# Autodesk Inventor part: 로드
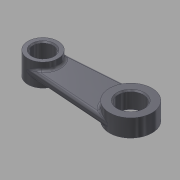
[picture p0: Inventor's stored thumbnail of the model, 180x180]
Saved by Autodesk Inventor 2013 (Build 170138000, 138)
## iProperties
Created: 2015-10
Part Number: 로드
Document SubType Name: Modeling
Designer: mdu
Density: 1 g/cm^3
Material: 강철, 연강
Mass: 2.59236 g
Surface Area: 22.2266 cm^2
Volume: 2.59236 cm^3
Author: mdu
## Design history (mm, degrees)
sketch "스케치1"
  geometry: L1 (13.821, 5.985)-(48.643, 8.478); L2 (48.643, -8.478)-(13.821, -5.985); C1 r 4 at (14.25, 0) reference; A1 r 6 centre (14.25, 0) between (13.821, 5.985) and (13.821, -5.985); A2 r 8.5 centre (49.25, 0) between (48.643, 8.478) and (48.643, -8.478); 1 further point
  constraints: 4 end point, 4 point on circle, 4 tangent, 2 centre point, 1 coincident, 1 horizontal alignment
  dimensions: "d0" = 12 diameter of A1; "d1" = 35 distance of A2.centre A1.centre; "d2" = 17 diameter of A2
  node "참조1"
extrude "돌출1" new body sketch "스케치1" distance "d3" = 9; taper "d4" = 0 deg
node "작업 평면1"
node "작업 평면2"
extrude "돌출2" join sketch "스케치1" stored distance "d7" = 10; taper "d8" = 0 deg
node "작업 평면3"
extrude "돌출3" join sketch "스케치1" stored distance "d10" = 10; taper "d11" = 0 deg
hole "구멍1" diameter "d14" = 10; stored, may be unused: countersink angle "d18" = 90 deg, drill point angle "d20" = 118 deg; dims "d12" = 10, "d13" = 10, "d15" = 6, "d16" = 4, "d17" = 2, "d19" = 8
fillet "모깎기1" dims "d21" = 1
chamfer "모따기1" distance "d22" = 0.5; stored, may be unused: second distance "d23" = 2, angle "d24" = 45 deg
chamfer "모따기2" distance "d25" = 0.5; stored, may be unused: second distance "d26" = 2, angle "d27" = 45 deg
node "솔리드1"
other parameters: "d5" = -6, "d6" = -3, "d9" = -4
